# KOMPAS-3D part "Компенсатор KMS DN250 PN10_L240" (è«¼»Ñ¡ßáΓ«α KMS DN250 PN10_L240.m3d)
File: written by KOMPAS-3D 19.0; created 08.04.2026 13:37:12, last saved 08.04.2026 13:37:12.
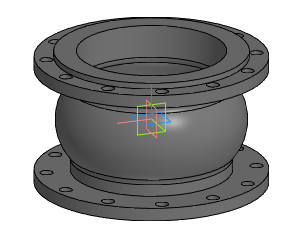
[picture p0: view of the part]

Document properties: Автор: Энергия; Полное имя файла: Z:\3.Личные\kachalov\3d для проектировщиков\7.1 Компенсатор\stp_Компенсатор KSM\Компенсатор KMS DN250 PN10_L240.m3d

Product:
- Part/product: Компенсатор KMS DN250 PN10_L240

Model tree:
1. Операция без истории:1  (labels: Компенсатор KMS DN250 PN10_L240)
